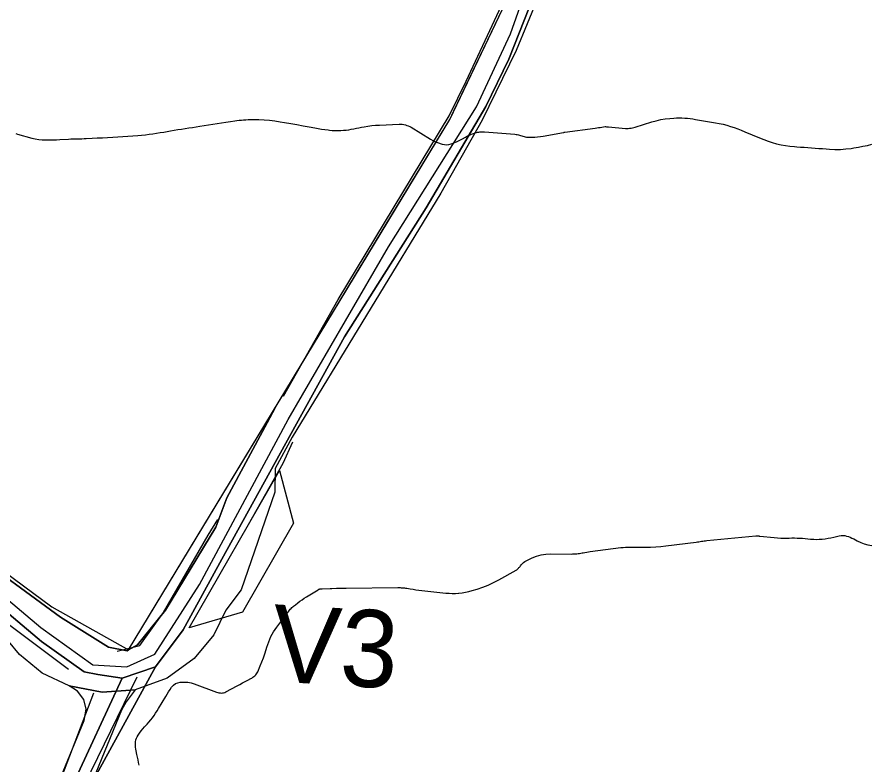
# Model space of a CAD drawing. Extents: x -629976 to -626966, y -1086511 to -1082952.
# Drawn here: x -628709.6 to -628543.5, y -1086224.5 to -1086079 of the extents above; entities that cross this region are included whole.
import ezdxf

# ---------------------------------------------------------------- set-up
doc = ezdxf.new("R2010")
doc.units = 0
for name, color, linetype in [('01_OBVOD PÚ', 7, 'Continuous'), ('01_PARCELY_NÁVRH_PC', 7, 'Continuous'), ('01_VRSTEVNICE', 7, 'Continuous'), ('02_KULTURY STAV', 7, 'Continuous'), ('03_PC_NÁVRH', 7, 'Continuous'), ('03_PC_OBJEKTY_NÁVRH', 7, 'Continuous'), ('04_ZPF_OP_ORGAN', 7, 'Continuous')]:
    doc.layers.add(name, color=color, linetype=linetype)

msp = doc.modelspace()

# ---------------------------------------------------------------- linework, layer by layer
at = {"layer": '01_OBVOD PÚ'}
msp.add_lwpolyline([(-628925.53, -1086073.14), (-628892, -1086083.87), (-628884.04, -1086087.41), (-628841.36, -1086099.35), (-628826.79, -1086105.69), (-628810.67, -1086116.47), (-628799.27, -1086126.34), (-628751.74, -1086154.07), (-628733.34, -1086168.35), (-628719.4, -1086181.46), (-628702.81, -1086193.72), (-628687.86, -1086202.09), (-628625.32, -1086098.87), (-628613.62, -1086074.4)], dxfattribs=at)
at = {"layer": '01_PARCELY_NÁVRH_PC'}
for points in [[(-628606.01, -1086069.84), (-628612.43, -1086085.45), (-628619.04, -1086099.04), (-628627.07, -1086113.22), (-628656.01, -1086160.7), (-628659.31, -1086166.78), (-628659.38, -1086171.41), (-628665.96, -1086190.42), (-628668.9, -1086194.35), (-628671.27, -1086199.19), (-628675.07, -1086203.79), (-628680.36, -1086207.58), (-628686.6, -1086209.86), (-628693.03, -1086210.36), (-628699.41, -1086209.13), (-628704.67, -1086206.62), (-628709.11, -1086203), (-628719.9, -1086190.06)], [(-628923.76, -1086074.5), (-628912.52, -1086079.35), (-628897.49, -1086085.32), (-628875.35, -1086091.95), (-628849.62, -1086098.57), (-628831.07, -1086105.65), (-628813.4, -1086115.33), (-628799.27, -1086126.34), (-628751.75, -1086154.07), (-628740.99, -1086164.03), (-628719.42, -1086182.39), (-628701.14, -1086195.76), (-628691.77, -1086201.59), (-628688.15, -1086202.32), (-628687.86, -1086202.09), (-628686.14, -1086201.11), (-628680.68, -1086194.35), (-628670.9, -1086178.21), (-628668.71, -1086172.52), (-628660.91, -1086157.89), (-628659.33, -1086155.01), (-628636.39, -1086117.14), (-628625.32, -1086098.87), (-628613.62, -1086074.4)], [(-628704.21, -1086234.59), (-628696.53, -1086215.82), (-628696.14, -1086213.67), (-628696.59, -1086211.77), (-628697.79, -1086210.12), (-628699.41, -1086209.13), (-628693.03, -1086210.36), (-628686.6, -1086209.86), (-628688.35, -1086212.22), (-628689.26, -1086213.86), (-628694.8, -1086227.43)]]:
    msp.add_lwpolyline(points, dxfattribs=at)
at = {"layer": '01_VRSTEVNICE'}
for points in [[(-628709.81, -1086101.64), (-628709.49, -1086101.75), (-628706.71, -1086102.5), (-628706.04, -1086102.65), (-628705.36, -1086102.77), (-628704.68, -1086102.83), (-628703.99, -1086102.86), (-628703.3, -1086102.86), (-628702.61, -1086102.84), (-628701.92, -1086102.82), (-628701.23, -1086102.79), (-628699.56, -1086102.7), (-628699.13, -1086102.68), (-628698.7, -1086102.66), (-628698.26, -1086102.65), (-628697.83, -1086102.64), (-628697.39, -1086102.63), (-628696.96, -1086102.62), (-628696.53, -1086102.61), (-628696.09, -1086102.59), (-628694.95, -1086102.54), (-628693.95, -1086102.49), (-628692.95, -1086102.44), (-628691.94, -1086102.38), (-628690.94, -1086102.32), (-628686.03, -1086101.98), (-628685.32, -1086101.92), (-628684.6, -1086101.85), (-628683.88, -1086101.76), (-628683.17, -1086101.67), (-628682.45, -1086101.56), (-628681.74, -1086101.45), (-628681.03, -1086101.33), (-628680.32, -1086101.21), (-628679.7, -1086101.1), (-628678.99, -1086100.98), (-628678.29, -1086100.86), (-628677.58, -1086100.74), (-628676.86, -1086100.63), (-628676.15, -1086100.53), (-628675.44, -1086100.42), (-628674.73, -1086100.31), (-628674.02, -1086100.2), (-628671.49, -1086099.8), (-628670.63, -1086099.66), (-628669.77, -1086099.53), (-628668.91, -1086099.41), (-628668.05, -1086099.28), (-628667.2, -1086099.16), (-628666.77, -1086099.1), (-628666.33, -1086099.05), (-628665.89, -1086099), (-628665.46, -1086098.96), (-628665.45, -1086098.96), (-628665.01, -1086098.93), (-628664.58, -1086098.91), (-628664.14, -1086098.9), (-628663.71, -1086098.9), (-628662.48, -1086098.92), (-628661.44, -1086098.96), (-628660.4, -1086099.04), (-628659.36, -1086099.16), (-628658.33, -1086099.32), (-628657.49, -1086099.47), (-628656.3, -1086099.68), (-628655.1, -1086099.89), (-628653.9, -1086100.11), (-628652.71, -1086100.32), (-628651.63, -1086100.52), (-628650.97, -1086100.63), (-628650.31, -1086100.74), (-628649.65, -1086100.83), (-628648.99, -1086100.92), (-628648.74, -1086100.95), (-628648.2, -1086101), (-628647.67, -1086101.03), (-628647.13, -1086101.04), (-628646.59, -1086101.03), (-628646.52, -1086101.03), (-628646.01, -1086100.99), (-628645.51, -1086100.95), (-628645.01, -1086100.87), (-628644.51, -1086100.78), (-628644.02, -1086100.68), (-628643.52, -1086100.59), (-628643.03, -1086100.49), (-628642.53, -1086100.4), (-628642.03, -1086100.3), (-628641.28, -1086100.18), (-628640.53, -1086100.08), (-628639.78, -1086100.01), (-628639.02, -1086099.97), (-628635.17, -1086099.81), (-628634.87, -1086099.81), (-628634.57, -1086099.83), (-628634.27, -1086099.88), (-628633.98, -1086099.94), (-628633.69, -1086100.03), (-628633.41, -1086100.13), (-628633.14, -1086100.26), (-628632.87, -1086100.4), (-628629.1, -1086102.69), (-628628.6, -1086102.97), (-628628.09, -1086103.22), (-628627.56, -1086103.43), (-628627.02, -1086103.62), (-628626.81, -1086103.68), (-628626.37, -1086103.77), (-628625.93, -1086103.8), (-628625.49, -1086103.75), (-628625.05, -1086103.63), (-628624.88, -1086103.57), (-628624.37, -1086103.37), (-628623.87, -1086103.15), (-628623.37, -1086102.91), (-628622.88, -1086102.65), (-628622.26, -1086102.3), (-628621.88, -1086102.1), (-628621.51, -1086101.92), (-628621.12, -1086101.76), (-628620.72, -1086101.62), (-628620.36, -1086101.5), (-628620.14, -1086101.43), (-628619.92, -1086101.38), (-628619.69, -1086101.34), (-628619.47, -1086101.31), (-628619.24, -1086101.3), (-628619.01, -1086101.29), (-628618.78, -1086101.3), (-628618.55, -1086101.31), (-628612.66, -1086101.76), (-628612.43, -1086101.78), (-628612.2, -1086101.82), (-628611.98, -1086101.87), (-628611.76, -1086101.94), (-628611.54, -1086102.01), (-628611.32, -1086102.08), (-628611.09, -1086102.15), (-628610.87, -1086102.22), (-628610.86, -1086102.22), (-628610.64, -1086102.27), (-628610.41, -1086102.32), (-628610.17, -1086102.34), (-628609.94, -1086102.35), (-628609.32, -1086102.34), (-628608.77, -1086102.33), (-628608.23, -1086102.29), (-628607.68, -1086102.22), (-628607.14, -1086102.14), (-628603.2, -1086101.41), (-628603.17, -1086101.4), (-628603.13, -1086101.4), (-628603.1, -1086101.39), (-628603.07, -1086101.38), (-628603.03, -1086101.38), (-628603, -1086101.37), (-628602.96, -1086101.37), (-628602.93, -1086101.36), (-628597.05, -1086100.55), (-628596.72, -1086100.51), (-628596.39, -1086100.46), (-628596.06, -1086100.42), (-628595.73, -1086100.37), (-628595.09, -1086100.28), (-628595.08, -1086100.28), (-628595.07, -1086100.28), (-628595.06, -1086100.28), (-628595.05, -1086100.28), (-628595.04, -1086100.28), (-628595.03, -1086100.28), (-628595.02, -1086100.28), (-628595.01, -1086100.28), (-628594.84, -1086100.3), (-628594.74, -1086100.31), (-628594.65, -1086100.32), (-628594.55, -1086100.33), (-628594.46, -1086100.34), (-628591.11, -1086100.63), (-628590.98, -1086100.63), (-628590.86, -1086100.63), (-628590.73, -1086100.63), (-628590.6, -1086100.62), (-628590.32, -1086100.59), (-628590.05, -1086100.55), (-628589.79, -1086100.5), (-628589.53, -1086100.44), (-628589.27, -1086100.36), (-628586.01, -1086099.36), (-628585.14, -1086099.12), (-628584.26, -1086098.92), (-628583.37, -1086098.77), (-628582.47, -1086098.67), (-628581.74, -1086098.61), (-628581.2, -1086098.57), (-628580.67, -1086098.56), (-628580.13, -1086098.57), (-628579.6, -1086098.61), (-628579.07, -1086098.66), (-628578.53, -1086098.72), (-628578, -1086098.79), (-628577.47, -1086098.87), (-628573.61, -1086099.53), (-628572.87, -1086099.67), (-628572.14, -1086099.83), (-628571.42, -1086100.02), (-628570.7, -1086100.23), (-628569.99, -1086100.46), (-628569.28, -1086100.71), (-628568.58, -1086100.98), (-628567.89, -1086101.26), (-628565.03, -1086102.47), (-628564.21, -1086102.79), (-628563.38, -1086103.09), (-628562.54, -1086103.36), (-628561.7, -1086103.6), (-628560.84, -1086103.8), (-628559.98, -1086103.97), (-628559.1, -1086104.09), (-628558.23, -1086104.17), (-628557.77, -1086104.2), (-628557.05, -1086104.25), (-628556.34, -1086104.3), (-628555.62, -1086104.35), (-628554.91, -1086104.4), (-628554.19, -1086104.45), (-628553.47, -1086104.51), (-628552.76, -1086104.56), (-628552.04, -1086104.61), (-628551.38, -1086104.66), (-628550.34, -1086104.7), (-628549.29, -1086104.7), (-628548.25, -1086104.63), (-628547.21, -1086104.51), (-628546.67, -1086104.42), (-628545.78, -1086104.28), (-628544.9, -1086104.11), (-628544.02, -1086103.92), (-628543.14, -1086103.71)], [(-628575.79, -1086180.91), (-628575.53, -1086180.88), (-628575.27, -1086180.85), (-628565.74, -1086179.93), (-628565.65, -1086179.93), (-628565.55, -1086179.92), (-628565.46, -1086179.92), (-628565.37, -1086179.93), (-628565.27, -1086179.93), (-628565.18, -1086179.94), (-628565.09, -1086179.95), (-628565, -1086179.95), (-628562.18, -1086180.24), (-628561.53, -1086180.3), (-628560.87, -1086180.34), (-628560.21, -1086180.35), (-628559.55, -1086180.35), (-628559.27, -1086180.34), (-628558.75, -1086180.33), (-628558.23, -1086180.33), (-628557.7, -1086180.34), (-628557.18, -1086180.36), (-628556.66, -1086180.38), (-628556.14, -1086180.42), (-628555.61, -1086180.47), (-628555.09, -1086180.53), (-628555.04, -1086180.54), (-628554.49, -1086180.59), (-628553.95, -1086180.61), (-628553.4, -1086180.59), (-628552.85, -1086180.55), (-628552.82, -1086180.54), (-628552.25, -1086180.47), (-628551.69, -1086180.38), (-628551.14, -1086180.27), (-628550.58, -1086180.15), (-628549.52, -1086179.9), (-628549.16, -1086179.85), (-628548.8, -1086179.83), (-628548.44, -1086179.87), (-628548.08, -1086179.95), (-628547.72, -1086180.06), (-628547.37, -1086180.19), (-628547.03, -1086180.34), (-628546.7, -1086180.51), (-628546.02, -1086180.87), (-628545.34, -1086181.19), (-628544.64, -1086181.46), (-628543.92, -1086181.66), (-628543.18, -1086181.81)], [(-628685.81, -1086224.52), (-628685.91, -1086224), (-628686.02, -1086223.48), (-628686.12, -1086222.96), (-628686.23, -1086222.44), (-628686.38, -1086221.75), (-628686.45, -1086221.4), (-628686.5, -1086221.04), (-628686.53, -1086220.69), (-628686.54, -1086220.33), (-628686.52, -1086219.98), (-628686.46, -1086219.64), (-628686.34, -1086219.32), (-628686.18, -1086219), (-628686.01, -1086218.72), (-628685.72, -1086218.29), (-628685.42, -1086217.87), (-628685.09, -1086217.47), (-628684.74, -1086217.08), (-628684.64, -1086216.97), (-628684.27, -1086216.57), (-628683.91, -1086216.16), (-628683.56, -1086215.74), (-628683.23, -1086215.32), (-628682.91, -1086214.88), (-628682.6, -1086214.43), (-628682.3, -1086213.97), (-628682.02, -1086213.51), (-628680.64, -1086211.18), (-628680.36, -1086210.72), (-628680.08, -1086210.26), (-628679.79, -1086209.81), (-628679.49, -1086209.36), (-628679.15, -1086208.98), (-628678.76, -1086208.68), (-628678.3, -1086208.49), (-628677.81, -1086208.38), (-628677.6, -1086208.37), (-628676.96, -1086208.36), (-628676.33, -1086208.41), (-628675.71, -1086208.53), (-628675.1, -1086208.71), (-628670.74, -1086210.32), (-628670.51, -1086210.39), (-628670.28, -1086210.44), (-628670.05, -1086210.48), (-628669.82, -1086210.5), (-628669.58, -1086210.49), (-628669.36, -1086210.46), (-628669.14, -1086210.39), (-628668.93, -1086210.3), (-628666.71, -1086209.1), (-628666.2, -1086208.83), (-628665.69, -1086208.55), (-628665.18, -1086208.28), (-628664.67, -1086208.01), (-628664.09, -1086207.7), (-628663.87, -1086207.58), (-628663.66, -1086207.44), (-628663.46, -1086207.3), (-628663.27, -1086207.14), (-628663.09, -1086206.97), (-628662.94, -1086206.78), (-628662.81, -1086206.58), (-628662.69, -1086206.36), (-628662.22, -1086205.24), (-628661.89, -1086204.45), (-628661.59, -1086203.65), (-628661.32, -1086202.85), (-628661.08, -1086202.03), (-628660.94, -1086201.56), (-628660.59, -1086200.53), (-628660.16, -1086199.53), (-628659.63, -1086198.59), (-628659.02, -1086197.68), (-628656.67, -1086194.54), (-628656.53, -1086194.37), (-628656.39, -1086194.2), (-628656.23, -1086194.04), (-628656.07, -1086193.89), (-628655.91, -1086193.74), (-628655.74, -1086193.59), (-628655.57, -1086193.45), (-628655.39, -1086193.32), (-628654.93, -1086192.96), (-628654.52, -1086192.65), (-628654.1, -1086192.35), (-628653.67, -1086192.06), (-628653.24, -1086191.78), (-628650.98, -1086190.4), (-628650.89, -1086190.35), (-628650.8, -1086190.31), (-628650.7, -1086190.27), (-628650.6, -1086190.25), (-628650.49, -1086190.23), (-628650.39, -1086190.22), (-628650.28, -1086190.21), (-628650.17, -1086190.21), (-628648.65, -1086190.18), (-628648.62, -1086190.18), (-628648.59, -1086190.17), (-628648.57, -1086190.17), (-628648.54, -1086190.17), (-628648.49, -1086190.17), (-628648.49, -1086190.17), (-628648.49, -1086190.17), (-628648.48, -1086190.17), (-628648.48, -1086190.17), (-628648.47, -1086190.16), (-628648.47, -1086190.16), (-628648.47, -1086190.16), (-628648.47, -1086190.16), (-628648.46, -1086190.16), (-628648.41, -1086190.16), (-628648.38, -1086190.15), (-628648.35, -1086190.15), (-628648.32, -1086190.15), (-628648.29, -1086190.15), (-628647.4, -1086190.12), (-628646.93, -1086190.11), (-628646.45, -1086190.09), (-628645.98, -1086190.09), (-628645.5, -1086190.08), (-628635.42, -1086189.98), (-628635.2, -1086189.98), (-628634.99, -1086189.99), (-628634.78, -1086190), (-628634.56, -1086190.01), (-628634.35, -1086190.03), (-628634.14, -1086190.05), (-628633.93, -1086190.08), (-628633.72, -1086190.11), (-628633.02, -1086190.22), (-628632.46, -1086190.31), (-628631.91, -1086190.39), (-628631.35, -1086190.46), (-628630.78, -1086190.53), (-628626.09, -1086191.05), (-628625.48, -1086191.09), (-628624.86, -1086191.12), (-628624.25, -1086191.11), (-628623.64, -1086191.08), (-628623.55, -1086191.07), (-628622.9, -1086190.99), (-628622.25, -1086190.89), (-628621.61, -1086190.75), (-628620.97, -1086190.57), (-628620.01, -1086190.28), (-628618.92, -1086189.91), (-628617.84, -1086189.49), (-628616.79, -1086189), (-628615.77, -1086188.47), (-628612.43, -1086186.59), (-628612.3, -1086186.51), (-628612.18, -1086186.42), (-628612.07, -1086186.32), (-628611.96, -1086186.21), (-628611.86, -1086186.09), (-628611.76, -1086185.98), (-628611.66, -1086185.86), (-628611.57, -1086185.73), (-628611.38, -1086185.5), (-628611.18, -1086185.27), (-628610.97, -1086185.07), (-628610.72, -1086184.9), (-628610.46, -1086184.76), (-628609.3, -1086184.22), (-628608.43, -1086183.89), (-628607.54, -1086183.63), (-628606.62, -1086183.5), (-628605.69, -1086183.44), (-628601.7, -1086183.45), (-628601.43, -1086183.44), (-628601.16, -1086183.44), (-628600.88, -1086183.42), (-628600.61, -1086183.4), (-628600.34, -1086183.37), (-628600.07, -1086183.34), (-628599.8, -1086183.29), (-628599.53, -1086183.24), (-628599.37, -1086183.2), (-628599.03, -1086183.13), (-628598.68, -1086183.06), (-628598.33, -1086183.01), (-628597.98, -1086182.96), (-628592.05, -1086182.2), (-628591.59, -1086182.16), (-628591.13, -1086182.12), (-628590.66, -1086182.1), (-628590.2, -1086182.1), (-628589.74, -1086182.1), (-628589.27, -1086182.11), (-628588.81, -1086182.11), (-628588.34, -1086182.11), (-628587.25, -1086182.12), (-628586.25, -1086182.11), (-628585.24, -1086182.07), (-628584.24, -1086181.98), (-628583.24, -1086181.88), (-628577.34, -1086181.12), (-628577.08, -1086181.08), (-628576.82, -1086181.05), (-628576.57, -1086181.01), (-628576.31, -1086180.98), (-628576.05, -1086180.94), (-628575.79, -1086180.91)]]:
    msp.add_lwpolyline(points, dxfattribs=at)
at = {"layer": '02_KULTURY STAV'}
for points in [[(-628607.89, -1086071.98), (-628613.84, -1086087.12), (-628618.34, -1086096.33), (-628629.94, -1086116.06), (-628645.85, -1086141.2), (-628669.74, -1086184.43), (-628677.22, -1086198.22), (-628682.6, -1086205.38), (-628689.13, -1086207.59), (-628693.82, -1086206.88), (-628696.53, -1086206.39), (-628704.82, -1086200.48), (-628743.46, -1086167.9), (-628755.6, -1086158.31), (-628769.25, -1086149.5), (-628798.93, -1086131.93), (-628816.52, -1086119.82), (-628832.62, -1086110.52), (-628850.57, -1086103.81), (-628876.89, -1086096.84), (-628892.67, -1086091.62), (-628914.44, -1086083), (-628947.05, -1086066.86)], [(-628536.6, -1086332.86), (-628544.68, -1086356.94), (-628552.14, -1086351.37), (-628581.57, -1086331.55), (-628601.92, -1086317.38), (-628623.11, -1086303.85), (-628646.4, -1086289.59), (-628683.89, -1086267.54), (-628700.67, -1086255.96), (-628704.72, -1086247.48), (-628696.33, -1086230.37), (-628682.6, -1086205.38), (-628677.22, -1086198.22), (-628669.74, -1086184.43), (-628645.85, -1086141.2), (-628629.94, -1086116.06), (-628618.34, -1086096.33), (-628613.84, -1086087.12), (-628607.89, -1086071.98)], [(-628799.27, -1086126.34), (-628751.75, -1086154.07), (-628740.99, -1086164.03), (-628719.42, -1086182.39), (-628701.14, -1086195.76), (-628691.77, -1086201.59), (-628688.15, -1086202.32), (-628687.86, -1086202.09), (-628686.14, -1086201.11), (-628680.68, -1086194.35), (-628670.9, -1086178.21), (-628668.71, -1086172.52), (-628660.91, -1086157.89), (-628659.33, -1086155.01), (-628636.39, -1086117.14), (-628625.32, -1086098.87), (-628624.52, -1086097.2), (-628622.97, -1086093.95), (-628613.62, -1086074.4)], [(-628798.93, -1086131.93), (-628769.25, -1086149.5), (-628755.6, -1086158.31), (-628743.46, -1086167.9), (-628704.82, -1086200.48), (-628696.53, -1086206.39), (-628693.82, -1086206.88), (-628689.13, -1086207.59), (-628698.93, -1086228.78), (-628706.64, -1086244.07), (-628708.63, -1086246.61), (-628722.11, -1086249.77), (-628754.72, -1086230.82), (-628768.48, -1086221.42), (-628775, -1086216.96), (-628781.95, -1086212.05), (-628824.11, -1086182.24)]]:
    msp.add_lwpolyline(points, dxfattribs=at)
for points in [[(-628751.75, -1086154.07), (-628733.34, -1086168.35), (-628719.4, -1086181.46), (-628702.81, -1086193.72), (-628687.86, -1086202.09), (-628688.15, -1086202.32), (-628691.77, -1086201.59), (-628701.14, -1086195.76), (-628719.42, -1086182.39), (-628740.99, -1086164.03)], [(-628687.86, -1086202.09), (-628659.33, -1086155.01), (-628660.91, -1086157.89), (-628668.71, -1086172.52), (-628670.9, -1086178.21), (-628680.68, -1086194.35), (-628686.14, -1086201.11)], [(-628708.63, -1086246.61), (-628706.64, -1086244.07), (-628698.93, -1086228.78), (-628689.13, -1086207.59), (-628682.6, -1086205.38), (-628696.33, -1086230.37), (-628704.72, -1086247.48), (-628700.67, -1086255.96), (-628683.89, -1086267.54), (-628646.4, -1086289.59), (-628623.11, -1086303.85), (-628601.92, -1086317.38), (-628581.57, -1086331.55), (-628552.14, -1086351.37), (-628544.68, -1086356.94), (-628546.36, -1086361.96), (-628555.29, -1086355.43), (-628584.41, -1086335.21), (-628605.14, -1086321.31), (-628622.53, -1086309.83), (-628649.74, -1086295.06), (-628685.74, -1086273.18), (-628702, -1086260.69), (-628708.39, -1086252.37)]]:
    msp.add_lwpolyline(points, close=True, dxfattribs=at)
at = {"layer": '03_PC_NÁVRH'}
for points in [[(-628951.02, -1086063.21), (-628916.5, -1086080.73), (-628909.36, -1086083.46), (-628892.07, -1086090.22), (-628871.77, -1086096.17), (-628849.15, -1086102.35), (-628834.4, -1086107.81), (-628820.31, -1086115.9), (-628800.02, -1086129.41), (-628754.91, -1086156.78), (-628730.54, -1086176.22), (-628704.92, -1086197.77), (-628694.84, -1086204.99), (-628688.22, -1086205.38), (-628682.76, -1086202.91), (-628674.05, -1086189.39), (-628656.81, -1086157.28), (-628637.25, -1086123.69), (-628620.1, -1086096.45), (-628613.49, -1086082.21), (-628605.63, -1086059.98)], [(-628686.25, -1086207.4), (-628701.6, -1086238.79), (-628702.17, -1086248.31), (-628700.67, -1086255.96), (-628695.95, -1086262.34), (-628684.75, -1086270.66), (-628658.69, -1086286), (-628637.18, -1086298.48), (-628620.38, -1086308.11), (-628609.73, -1086315.31), (-628564.59, -1086346.06), (-628545.49, -1086359.19)]]:
    msp.add_lwpolyline(points, dxfattribs=at)
at = {"layer": '03_PC_OBJEKTY_NÁVRH'}
for points in [[(-628657.72, -1086152.76), (-628647.09, -1086133.93), (-628625.46, -1086098.18), (-628622.16, -1086091.42), (-628615.74, -1086077.65), (-628612.1, -1086067.96), (-628606.44, -1086050.16), (-628597.86, -1086022.49), (-628578.48, -1085959.51), (-628566.81, -1085922.32), (-628561.55, -1085905.52), (-628555.05, -1085887.59), (-628541.24, -1085849.89), (-628525.99, -1085807.83), (-628509.4, -1085759.65), (-628502.31, -1085738.52), (-628493.7, -1085711.62), (-628484.82, -1085686.08)], [(-628699.54, -1086205.91), (-628713.61, -1086195.39), (-628732.73, -1086179.1), (-628754.32, -1086161.76), (-628762.5, -1086156.43), (-628775.01, -1086148.94), (-628810.56, -1086127.24), (-628829.22, -1086114.8), (-628836.5, -1086110.74), (-628851.67, -1086105.35), (-628876.02, -1086099.38), (-628891.46, -1086094.6), (-628922.38, -1086082.81), (-628949.48, -1086068.21)], [(-628664.54, -1086177.69), (-628657.77, -1086165.78), (-628655.87, -1086161.65)], [(-628690.09, -1086202.37), (-628685.65, -1086201.25), (-628681.09, -1086194.8), (-628672.37, -1086179.79), (-628670.47, -1086176.71)], [(-628694.72, -1086210.55), (-628702.48, -1086230.94), (-628697.47, -1086237.27), (-628698.1, -1086247.75), (-628697.34, -1086253.08), (-628695.09, -1086257.73), (-628689.18, -1086262.81)]]:
    msp.add_lwpolyline(points, dxfattribs=at)
msp.add_lwpolyline([(-628658.5, -1086167.21), (-628655.73, -1086177.45), (-628665.69, -1086194.79), (-628676.06, -1086197.79)], close=True, dxfattribs=at)
at = {"layer": '04_ZPF_OP_ORGAN'}
for points in [[(-628536.6, -1086332.86), (-628544.67, -1086356.94), (-628552.14, -1086351.37), (-628581.57, -1086331.55), (-628601.92, -1086317.38), (-628623.11, -1086303.85), (-628646.4, -1086289.59), (-628683.89, -1086267.54), (-628700.67, -1086255.96), (-628704.72, -1086247.48), (-628696.33, -1086230.37), (-628682.6, -1086205.38), (-628677.22, -1086198.22), (-628669.74, -1086184.43), (-628645.85, -1086141.2), (-628629.94, -1086116.06), (-628618.34, -1086096.33), (-628613.84, -1086087.12), (-628607.89, -1086071.98)], [(-628798.93, -1086131.93), (-628769.25, -1086149.5), (-628755.6, -1086158.31), (-628743.46, -1086167.9), (-628704.82, -1086200.48), (-628696.53, -1086206.39), (-628693.82, -1086206.88), (-628689.13, -1086207.59), (-628698.93, -1086228.78), (-628706.64, -1086244.07), (-628708.63, -1086246.61), (-628722.11, -1086249.77), (-628754.72, -1086230.82), (-628768.48, -1086221.42), (-628775, -1086216.96), (-628781.95, -1086212.05), (-628824.11, -1086182.24)]]:
    msp.add_lwpolyline(points, dxfattribs=at)

# ---------------------------------------------------------------- texts
at = {"layer": '03_PC_OBJEKTY_NÁVRH'}
msp.add_text('V3', height=15, rotation=356.6285, dxfattribs=at).set_placement((-628660.33, -1086208.21))

doc.saveas('drawing.dxf')
